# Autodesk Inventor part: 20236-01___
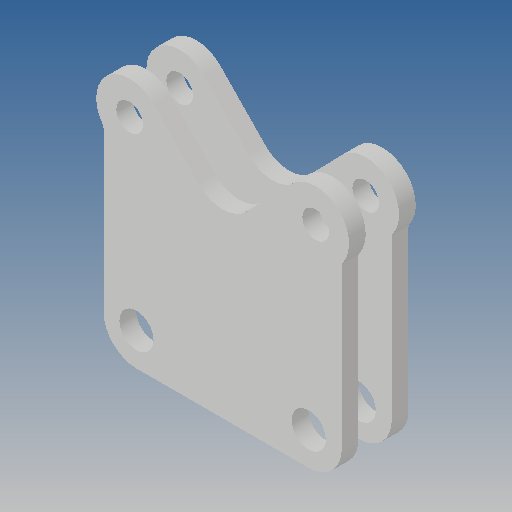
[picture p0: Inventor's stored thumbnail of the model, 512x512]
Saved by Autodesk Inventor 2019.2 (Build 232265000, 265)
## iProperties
Created: 2010-06
Part Number: 20236-01___
Material: Ogólny
Document SubType Name: Modeling
Designer: CADENGINEERING4
Density: 1 g/cm^3
Appearance: Domyślna
Author: CADENGINEERING4
Revision Number: ANY
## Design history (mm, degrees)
feature "NONE"
feature "NONE:1"
node "Bryła1"
node "Bryła2"
